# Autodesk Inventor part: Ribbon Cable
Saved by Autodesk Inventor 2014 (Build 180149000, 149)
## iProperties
Created: 2006-11
Part Number: Ribbon Cable
Document SubType Name: Modeling
Designer: floress
Density: 1 g/cm^3
Material: Generic
Appearance: Default
Author: floress
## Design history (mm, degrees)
